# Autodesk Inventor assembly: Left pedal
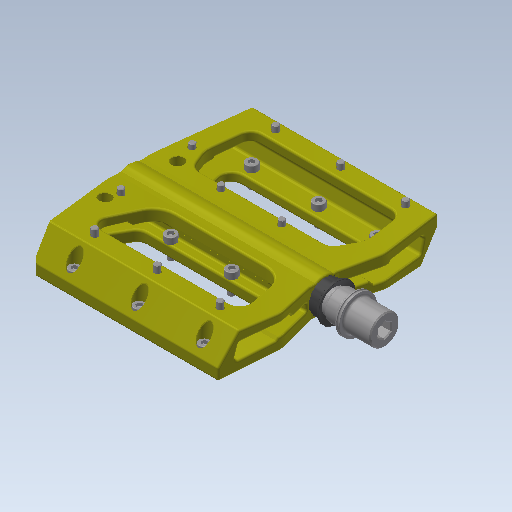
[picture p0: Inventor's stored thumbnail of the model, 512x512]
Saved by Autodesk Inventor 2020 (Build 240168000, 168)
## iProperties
Created: 2017-10
Part Number: Left pedal
Material: Ogólny
Document SubType Name: Assembly
Designer: Tomasz
Sending System: SolidWorks 2017
Last Author: Tomasz
Last Saved: 2017-11-20
Author: Tomasz
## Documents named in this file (3)
- C:\Users\bruno\Documents\1-Cours-2020-21\1STI2D-2020-21\IT\6. Antivol\Inventor-Antivol\INVENTOR 2018_Steel Hardtail B+\Left pedal.iam
- C:\Users\bruno\Documents\1-Cours-2020-21\1STI2D-2020-21\IT\6. Antivol\Inventor-Antivol\INVENTOR 2018_Steel Hardtail B+\Kopia Left pedal.iam^Left pedal.iam
- C:\Users\bruno\Documents\1-Cours-2020-21\1STI2D-2020-21\IT\6. Antivol\Inventor-Antivol\INVENTOR 2018_Steel Hardtail B+\686-2RS bearing.iam
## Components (3 placed, 2 different names)
1. Kopia Left pedal.iam^Left pedal:1 [sub-assembly]
2. 686-2RS bearing:1 [sub-assembly]
3. 686-2RS bearing:2 [sub-assembly]
